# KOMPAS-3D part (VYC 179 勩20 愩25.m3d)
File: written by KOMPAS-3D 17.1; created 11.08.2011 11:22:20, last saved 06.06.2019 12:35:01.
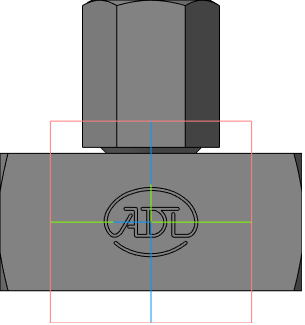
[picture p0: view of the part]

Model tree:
1. Плоскость XY
2. Плоскость ZX
3. Плоскость ZY
4. Ось X
5. Ось Y
6. Ось Z
7. Начало координат
8. Операция без истории:2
